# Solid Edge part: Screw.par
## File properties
Title: Screw
Author: Robert a Rhodes jr
Template: Normal.par
Last saved by: Rajat Kamboj
Revision: 15
Application: Solid Edge
Accuracy: 0.99
Material: aluminum
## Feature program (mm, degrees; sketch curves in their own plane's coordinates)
sketch for "unnamed Protrusion 1" plane through (0, 0, 0) normal (0, -1, 0) x-axis (1, 0, 0)
  circle centre (0, 0) radius 12.5
extrude "unnamed Protrusion 1" add finite 25 along +normal
sketch for "ExtrudedProtrusion_2" plane through (0, -25, 0) normal (0, -1, 0) x-axis (1, 0, 0)
  circle centre (0, 0) radius 10
extrude "ExtrudedProtrusion_2" add finite 96 along +normal
sketch for "ExtrudedProtrusion_3" plane through (0, -121, 0) normal (0, -1, 0) x-axis (1, 0, 0)
  circle centre (0, 0) radius 6
extrude "ExtrudedProtrusion_3" add finite 4 along +normal
sketch for "ExtrudedProtrusion_4" plane through (0, -125, 0) normal (0, -1, 0) x-axis (1, 0, 0)
  circle centre (0, 0) radius 4
extrude "ExtrudedProtrusion_4" add finite 6 along +normal
sketch for "unnamed RevolvedProtrusion 1" plane through (0, 0, 0) normal (0, 0, 1) x-axis (1, 0, 0)
  line (0, -131) -> (6, -131)
  line (6, -131) -> (6, -141)
  line (6, -141) -> (0, -143.8522)
  line (0, -143.8522) -> (0, -131)
revolve "unnamed RevolvedProtrusion 1" add full turn 360 deg about sketch line (0, -131) -> (0, -106.3065)
sketch for "ExtrudedCutout_1" plane through (0, 0, 0) normal (1, 0, 0) x-axis (0, 1, 0)
  circle centre (-13, 0) radius 5.5
extrude "ExtrudedCutout_1" cut finite 222.1 symmetric
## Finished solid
Body 1: solid body, 12 faces, 12 edges, 1 vertex.
  Faces by surface: cylinder 6, plane 5, cone 1
  Edges by curve: circle 10, intersection 2
Bounding box of the edges (mm): 25.000 x 141.000 x 25.000, from (-12.5, -141, -12.5) to (12.5, 0, 12.5).
Cylindrical faces by radius (mm): R4 x1, R5.5 x1, R6 x2, R10 x1, R12.5 x1
Conical faces (half-angle, radius in mm at the cone's reference point): 64.5754 deg R6 x1
Planar faces by outward normal: +y 2, -y 3
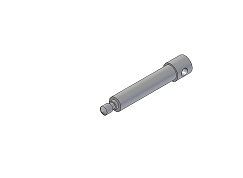
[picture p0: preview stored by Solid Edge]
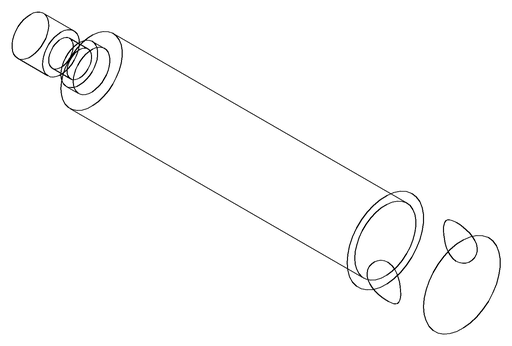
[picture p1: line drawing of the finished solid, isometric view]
